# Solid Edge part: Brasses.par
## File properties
Author: Deepak Maini
Template: normal.par
Last saved by: Administrator
Revision: 4
Application: Solid Edge
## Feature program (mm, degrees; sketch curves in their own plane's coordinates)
sketch for "unnamed RevolvedProtrusion 1" plane through (0, 0, 0) normal (0, -1, 0) x-axis (1, 0, 0)
  line (-32.5, 0) -> (-32.5, 32)
  line (-32.5, 32) -> (-23, 32)
  line (-23, 32) -> (-23, 24)
  line (-23, 24) -> (-14, 24)
  line (-14, 24) -> (-14, 22)
  line (-14, 22) -> (14, 22)
  line (14, 22) -> (14, 24)
  line (14, 24) -> (23, 24)
  line (23, 24) -> (23, 32)
  line (23, 32) -> (32.5, 32)
  line (32.5, 32) -> (32.5, 0)
  line (32.5, 0) -> (-32.5, 0)
revolve "unnamed RevolvedProtrusion 1" add finite 360 deg
sketch for "unnamed Protrusion 1" plane through (0, 0, 0) normal (0, 0, 1) x-axis (1, 0, 0)
  circle centre (0, 0) radius 4
extrude "unnamed Protrusion 1" add finite 30 along -normal
sketch for "unnamed Hole 1" plane through (0, 0, -30) normal (0, 0, -1) x-axis (1, 0, 0)
  hole centre (0, 0) bore radius 3
hole "unnamed Hole 1" through
sketch for "unnamed Hole 2" plane through (32.5, 0, 0) normal (1, 0, 0) x-axis (0, 1, 0)
  hole centre (0, 0) bore radius 16
hole "unnamed Hole 2" through
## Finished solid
Body 1: solid body, 16 faces, 18 edges, 0 vertices.
  Faces by surface: cylinder 9, plane 7
  Edges by curve: circle 14, intersection 4
Bounding box of the edges (mm): 65.000 x 64.000 x 64.000, from (-32.5, -32, -32) to (32.5, 32, 32).
Cylindrical faces by radius (mm): R3 x2, R4 x1, R16 x1, R22 x1, R24 x2, R32 x2
Planar faces by outward normal: +x 3, -x 3, -z 1
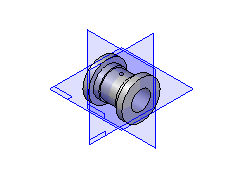
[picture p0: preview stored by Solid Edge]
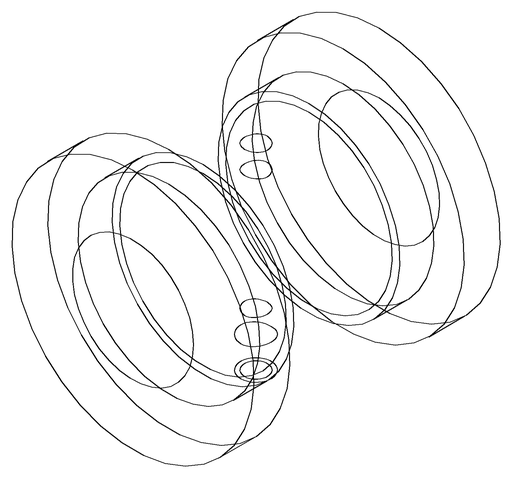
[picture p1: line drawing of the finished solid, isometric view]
